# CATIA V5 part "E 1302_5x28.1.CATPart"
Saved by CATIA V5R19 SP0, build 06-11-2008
Part number: E 1302_5x28.1
Nomenclature: E 1302_5x28
Source: Unknown
Description: PART-E 1302_5x28-DESC
Bounding box of the stored display mesh (mm): x -2.5 to 2.5, y -2.5 to 2.5, z 0 to 28
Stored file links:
  C:\Users\jsmid\Desktop\DP_Smidak_Forma LEGO\E 1302_5x28.1.CATPart
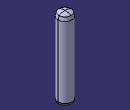
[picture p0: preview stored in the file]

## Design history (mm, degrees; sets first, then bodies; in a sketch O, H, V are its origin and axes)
Body1 "E 1302_5x28" (main body)
  Solid1: solid without history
